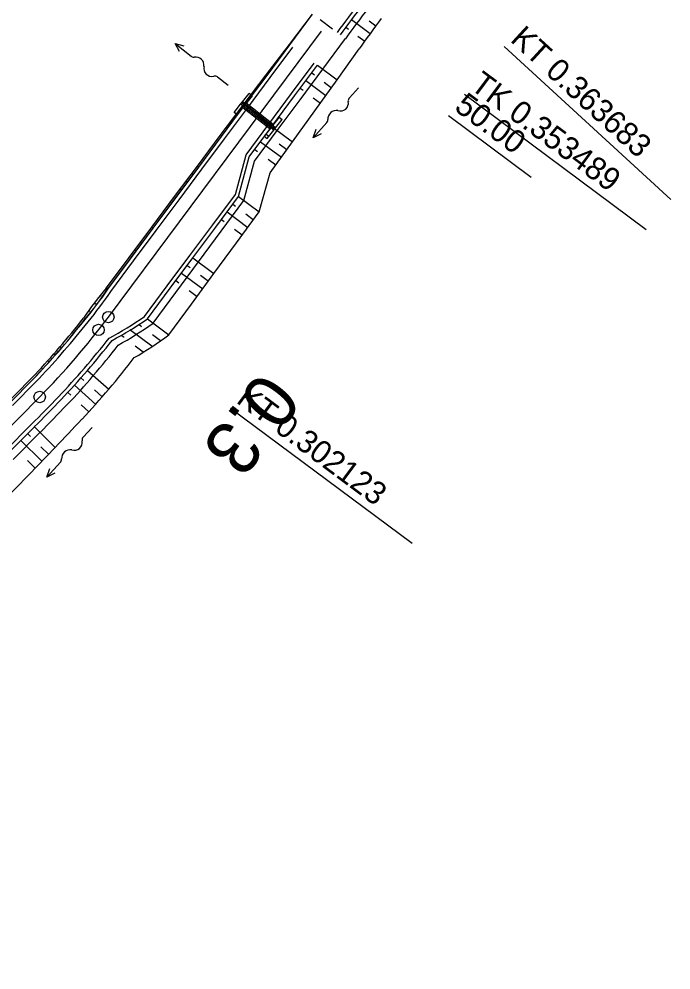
# Model space of a CAD drawing. Extents: x -481656 to -478728, y -1113199 to -1110710.
# Drawn here: x -479712.7 to -479627.2, y -1111634.8 to -1111510 of the extents above; entities that cross this region are included whole.
import ezdxf

# ---------------------------------------------------------------- set-up
doc = ezdxf.new("R2010")
doc.units = 0
for name, color, linetype in [('C5_HATCH_SLOPE_L', 7, 'Continuous'), ('C5_HATCH_SLOPE_R', 7, 'Continuous'), ('C5_HECTOMETRY', 7, 'Continuous'), ('C5_HLBODY', 7, 'Continuous'), ('C5_HRANA_TELESO', 7, 'Continuous'), ('C5_KORUNA', 7, 'Continuous'), ('C5_OSA', 7, 'Continuous'), ('C5_PRIKOP', 7, 'Continuous'), ('C5_STANICENI', 7, 'Continuous'), ('C5_ZPEVKRAJ', 7, 'Continuous'), ('DRENÁŽ', 7, 'Continuous'), ('PLYN', 7, 'Continuous'), ('ŽLAB', 7, 'Continuous')]:
    doc.layers.add(name, color=color, linetype=linetype)

# ---------------------------------------------------------------- blocks, each defined once
blk = doc.blocks.new('A$C716')
at = {"layer": 'ŽLAB'}
for p, q in [((-5.015, 2.333), (-4.471, 3.623)), ((-4.01, 3.428), (-4.554, 2.138)), ((-4.01, 3.428), (-4.471, 3.623)), ((-5.715, 0.674), (-5.17, 1.964)), ((-4.71, 1.77), (-5.254, 0.48)), ((-0.078, -0.184), (-5.171, 1.964)), ((-5.17, 1.964), (-5.015, 2.333)), ((-4.71, 1.77), (-5.17, 1.964)), ((0, 0), (-5.093, 2.148)), ((-5.015, 2.333), (-0.383, 0.379)), ((-4.554, 2.138), (-5.015, 2.333)), ((-4.768, 1.632), (-0.597, -0.128)), ((-0.325, 0.517), (-4.496, 2.277)), ((0.161, 1.669), (-0.383, 0.379)), ((0.078, 0.184), (0.622, 1.474)), ((0.161, 1.669), (0.622, 1.474)), ((-5.254, 0.48), (-5.715, 0.674)), ((-0.538, 0.01), (-1.083, -1.28)), ((-0.078, -0.184), (-0.999, 0.204)), ((0.078, 0.184), (-0.844, 0.573)), ((-0.538, 0.01), (-0.383, 0.379)), ((-0.078, -0.184), (0.078, 0.184)), ((-0.622, -1.474), (-0.078, -0.184)), ((-1.083, -1.28), (-0.622, -1.474))]:
    blk.add_line(p, q, dxfattribs=at)
blk = doc.blocks.new('A$C70B')
at = {"layer": 'DRENÁŽ'}
for p, q in [((0.87, 0), (-0.87, 0)), ((6.86, 0.43), (7.97, 0)), ((7.97, 0), (5.28, 0)), ((7.97, 0), (6.86, -0.48))]:
    blk.add_line(p, q, dxfattribs=at)
for centre, radius, start, end in [((0.87, 0.58), 0.582, 269.6924, 322.7901), ((2.17, -0.42), 1.05, 24.4039, 142.0836), ((4.08, 0.59), 1.11, 210.8873, 317.3707), ((5.32, -0.64), 0.636, 85.9766, 131.7248)]:
    blk.add_arc(centre, radius, start, end, dxfattribs=at)

msp = doc.modelspace()

# ---------------------------------------------------------------- linework, layer by layer
at = {"layer": 'C5_HATCH_SLOPE_L'}
for p, q in [((-479677.2, -1111513.36), (-479677.31, -1111513.28)), ((-479678.7, -1111515.37), (-479678.83, -1111515.27)), ((-479678.01, -1111514.32), (-479678.07, -1111514.28)), ((-479677.95, -1111514.37), (-479677.96, -1111514.36)), ((-479679.52, -1111516.31), (-479679.59, -1111516.26)), ((-479679.45, -1111516.37), (-479679.45, -1111516.37)), ((-479683.18, -1111521.38), (-479683.37, -1111521.24)), ((-479684.02, -1111522.31), (-479684.11, -1111522.24)), ((-479683.93, -1111522.39), (-479683.93, -1111522.38)), ((-479684.67, -1111523.39), (-479684.86, -1111523.25)), ((-479685.52, -1111524.32), (-479685.61, -1111524.25)), ((-479685.42, -1111524.39), (-479685.42, -1111524.39)), ((-479690, -1111530.33), (-479690.09, -1111530.26)), ((-479689.15, -1111529.4), (-479689.34, -1111529.26)), ((-479690.65, -1111531.41), (-479690.84, -1111531.26)), ((-479689.9, -1111530.4), (-479689.9, -1111530.4)), ((-479691.49, -1111532.33), (-479691.59, -1111532.27)), ((-479691.39, -1111532.41), (-479691.4, -1111532.41)), ((-479695.13, -1111537.42), (-479695.32, -1111537.28)), ((-479695.98, -1111538.35), (-479696.07, -1111538.28)), ((-479695.88, -1111538.42), (-479695.88, -1111538.42)), ((-479696.62, -1111539.43), (-479696.82, -1111539.28)), ((-479697.47, -1111540.35), (-479697.56, -1111540.28)), ((-479697.37, -1111540.43), (-479697.37, -1111540.42)), ((-479701.95, -1111546.36), (-479702.05, -1111546.29)), ((-479701.85, -1111546.44), (-479701.85, -1111546.44)), ((-479701.1, -1111545.44), (-479701.3, -1111545.29)), ((-479702.6, -1111547.44), (-479702.8, -1111547.29)), ((-479703.44, -1111548.35), (-479703.54, -1111548.28)), ((-479703.34, -1111548.43), (-479703.34, -1111548.43)), ((-479708.08, -1111554.01), (-479708.17, -1111553.93)), ((-479707.18, -1111553.18), (-479707.37, -1111553.01)), ((-479708.8, -1111555.01), (-479708.98, -1111554.84)), ((-479707.98, -1111554.1), (-479707.98, -1111554.09)), ((-479709.72, -1111555.82), (-479709.81, -1111555.73)), ((-479709.62, -1111555.91), (-479709.63, -1111555.9))]:
    msp.add_line(p, q, dxfattribs=at)
at = {"layer": 'C5_HATCH_SLOPE_R'}
for p, q in [((-479669.11, -1111510.04), (-479666.66, -1111511.87)), ((-479666.81, -1111510.21), (-479665.93, -1111510.87)), ((-479669.86, -1111511.04), (-479669.52, -1111511.29)), ((-479668.28, -1111512.22), (-479667.39, -1111512.89)), ((-479673.6, -1111516.05), (-479671.02, -1111517.97)), ((-479674.34, -1111517.05), (-479673.99, -1111517.31)), ((-479675.09, -1111518.06), (-479672.48, -1111520.01)), ((-479672.7, -1111518.28), (-479671.75, -1111518.99)), ((-479675.84, -1111519.06), (-479675.48, -1111519.32)), ((-479674.17, -1111520.3), (-479673.2, -1111521.02)), ((-479680.32, -1111525.07), (-479679.96, -1111525.34)), ((-479679.57, -1111524.07), (-479676.85, -1111526.09)), ((-479681.06, -1111526.08), (-479678.32, -1111528.12)), ((-479678.59, -1111526.36), (-479677.59, -1111527.11)), ((-479681.81, -1111527.08), (-479681.45, -1111527.35)), ((-479680.07, -1111528.38), (-479679.05, -1111529.13)), ((-479683.94, -1111533.28), (-479681.23, -1111535.3)), ((-479684.69, -1111534.29), (-479684.33, -1111534.55)), ((-479686.18, -1111536.29), (-479685.83, -1111536.56)), ((-479685.43, -1111535.29), (-479682.71, -1111537.32)), ((-479682.98, -1111535.56), (-479681.97, -1111536.31)), ((-479684.46, -1111537.57), (-479683.45, -1111538.32)), ((-479689.92, -1111541.3), (-479687.16, -1111543.36)), ((-479690.66, -1111542.31), (-479690.3, -1111542.58)), ((-479691.41, -1111543.31), (-479688.63, -1111545.38)), ((-479688.91, -1111543.61), (-479687.89, -1111544.37)), ((-479692.16, -1111544.31), (-479691.79, -1111544.59)), ((-479690.4, -1111545.62), (-479689.37, -1111546.38)), ((-479697.04, -1111550.03), (-479696.66, -1111550.31)), ((-479695.89, -1111549.32), (-479693.07, -1111551.42)), ((-479699.35, -1111551.45), (-479698.96, -1111551.75)), ((-479698.19, -1111550.73), (-479695.3, -1111552.88)), ((-479695.23, -1111551.37), (-479694.19, -1111552.15)), ((-479697.51, -1111552.85), (-479696.46, -1111553.65)), ((-479703.77, -1111556.11), (-479700.95, -1111558.55)), ((-479704.61, -1111557.08), (-479704.23, -1111557.42)), ((-479705.46, -1111558.03), (-479702.68, -1111560.55)), ((-479702.83, -1111558.65), (-479701.81, -1111559.55)), ((-479706.33, -1111558.97), (-479705.95, -1111559.32)), ((-479704.57, -1111560.6), (-479703.57, -1111561.53)), ((-479710.73, -1111563.5), (-479708, -1111566.2)), ((-479711.61, -1111564.39), (-479711.24, -1111564.76)), ((-479712.49, -1111565.28), (-479709.73, -1111568)), ((-479709.86, -1111566.11), (-479708.87, -1111567.1)), ((-479711.61, -1111567.91), (-479710.6, -1111568.9))]:
    msp.add_line(p, q, dxfattribs=at)
at = {"layer": 'C5_HECTOMETRY'}
msp.add_circle((-479702.3, -1111550.78), 0.75, dxfattribs=at)
at = {"layer": 'C5_HLBODY'}
for p, q in [((-479649.09, -1111513.57), (-479627.21, -1111533.65)), ((-479654.29, -1111519.85), (-479630.47, -1111537.59)), ((-479684.98, -1111561.04), (-479661.16, -1111578.78))]:
    msp.add_line(p, q, dxfattribs=at)
for centre in [(-479701.02, -1111549.09), (-479710.03, -1111559.58)]:
    msp.add_circle(centre, 0.75, dxfattribs=at)
at = {"layer": 'C5_HRANA_TELESO'}
for p, q in [((-479677.27, -1111513.31), (-479674.23, -1111509.34)), ((-479680.31, -1111517.28), (-479677.27, -1111513.31)), ((-479671.02, -1111517.97), (-479668.11, -1111513.9)), ((-479683.34, -1111521.26), (-479680.31, -1111517.28)), ((-479673.93, -1111522.04), (-479671.02, -1111517.97)), ((-479686.33, -1111525.27), (-479683.34, -1111521.26)), ((-479676.85, -1111526.09), (-479673.93, -1111522.04)), ((-479689.33, -1111529.27), (-479686.33, -1111525.27)), ((-479679.79, -1111530.15), (-479676.85, -1111526.09)), ((-479692.32, -1111533.28), (-479689.33, -1111529.27)), ((-479681.23, -1111535.3), (-479679.79, -1111530.15)), ((-479695.32, -1111537.28), (-479692.32, -1111533.28)), ((-479684.19, -1111539.33), (-479681.23, -1111535.3)), ((-479698.31, -1111541.28), (-479695.32, -1111537.28)), ((-479687.16, -1111543.36), (-479684.19, -1111539.33)), ((-479701.31, -1111545.29), (-479698.31, -1111541.28)), ((-479690.11, -1111547.39), (-479687.16, -1111543.36)), ((-479693.07, -1111551.42), (-479690.11, -1111547.39)), ((-479711.47, -1111569.8), (-479708, -1111566.2)), ((-479714.93, -1111573.4), (-479711.47, -1111569.8))]:
    msp.add_line(p, q, dxfattribs=at)
for centre, radius, start, end in [((-479436.28, -1111678.25), 284.18, 143.6746, 144.6667), ((-479663.95, -1111576.59), 48.74, 140.0386, 145.8556), ((-479781.28, -1111489.44), 97.49, 319.3, 322.1647), ((-479724.41, -1111508.73), 52.96, 300.3782, 306.281), ((-479781.31, -1111489.46), 97.5, 316.4548, 319.3196), ((-479781.84, -1111490.12), 105.95, 319.7732, 322.6381), ((-479921.26, -1111353.66), 292.5, 315.0894, 316.0604), ((-479781.9, -1111490.11), 106, 316.9239, 319.7889), ((-479936.09, -1111344.5), 318.07, 315.8147, 316.7342)]:
    msp.add_arc(centre, radius, start, end, dxfattribs=at)
at = {"layer": 'C5_KORUNA'}
for p, q in [((-479680.19, -1111517.37), (-479677.2, -1111513.36)), ((-479676.58, -1111520.06), (-479673.6, -1111516.05)), ((-479683.18, -1111521.38), (-479680.19, -1111517.37)), ((-479679.57, -1111524.07), (-479676.58, -1111520.06)), ((-479686.17, -1111525.39), (-479683.18, -1111521.38)), ((-479682.56, -1111528.08), (-479679.57, -1111524.07)), ((-479689.15, -1111529.4), (-479686.17, -1111525.39)), ((-479683.94, -1111533.28), (-479682.56, -1111528.08)), ((-479692.14, -1111533.41), (-479689.15, -1111529.4)), ((-479695.13, -1111537.42), (-479692.14, -1111533.41)), ((-479686.93, -1111537.29), (-479683.94, -1111533.28)), ((-479698.12, -1111541.43), (-479695.13, -1111537.42)), ((-479689.92, -1111541.3), (-479686.93, -1111537.29)), ((-479701.1, -1111545.44), (-479698.12, -1111541.43)), ((-479692.9, -1111545.31), (-479689.92, -1111541.3)), ((-479695.89, -1111549.32), (-479692.9, -1111545.31)), ((-479714.24, -1111567.06), (-479710.73, -1111563.5))]:
    msp.add_line(p, q, dxfattribs=at)
for centre, radius, start, end in [((-479434.37, -1111685.79), 293.25, 142.6969, 143.6672), ((-479741.6, -1111518.08), 48.88, 320.1521, 325.9599), ((-479781.21, -1111489.34), 97.75, 319.2297, 322.0945), ((-479724.86, -1111507.2), 51.12, 298.4217, 304.5189), ((-479781.21, -1111489.34), 102.25, 319.2297, 322.0945), ((-479781.21, -1111489.34), 97.75, 316.3649, 319.2297), ((-479781.21, -1111489.34), 102.25, 316.3649, 319.2297), ((-479921.52, -1111353.2), 293.25, 315.0613, 316.0307), ((-479927.94, -1111346.9), 306.75, 315.0804, 316.0216)]:
    msp.add_arc(centre, radius, start, end, dxfattribs=at)
at = {"layer": 'C5_OSA'}
for p, q in [((-479701.02, -1111549.09), (-479673.05, -1111511.56)), ((-479784.24, -1111634.78), (-479710.03, -1111559.58))]:
    msp.add_line(p, q, dxfattribs=at)
msp.add_arc((-479781.21, -1111489.34), 100, 315.3788, 323.3108, dxfattribs=at)
at = {"layer": 'C5_PRIKOP'}
for p, q in [((-479677.21, -1111513.36), (-479674.23, -1111509.35)), ((-479672.9, -1111516.57), (-479669.92, -1111512.55)), ((-479680.2, -1111517.37), (-479677.21, -1111513.36)), ((-479683.19, -1111521.38), (-479680.2, -1111517.37)), ((-479675.87, -1111520.59), (-479672.9, -1111516.57)), ((-479686.17, -1111525.39), (-479683.19, -1111521.38)), ((-479678.85, -1111524.61), (-479675.87, -1111520.59)), ((-479681.83, -1111528.63), (-479678.85, -1111524.61)), ((-479689.16, -1111529.4), (-479686.17, -1111525.39)), ((-479683.24, -1111533.81), (-479681.83, -1111528.63)), ((-479692.15, -1111533.41), (-479689.16, -1111529.4)), ((-479695.14, -1111537.41), (-479692.15, -1111533.41)), ((-479686.21, -1111537.83), (-479683.24, -1111533.81)), ((-479698.12, -1111541.42), (-479695.14, -1111537.41)), ((-479689.19, -1111541.85), (-479686.21, -1111537.83)), ((-479701.11, -1111545.43), (-479698.12, -1111541.42)), ((-479692.16, -1111545.86), (-479689.19, -1111541.85)), ((-479695.14, -1111549.88), (-479692.16, -1111545.86)), ((-479713.49, -1111567.8), (-479709.99, -1111564.24))]:
    msp.add_line(p, q, dxfattribs=at)
for centre, radius, start, end in [((-479435.19, -1111684.09), 290.73, 142.8656, 143.8418), ((-479741.61, -1111518.08), 48.87, 320.1519, 325.9601), ((-479781.21, -1111489.34), 97.74, 319.2297, 322.0945), ((-479724.9, -1111507.7), 51.63, 299.1686, 305.2022), ((-479781.21, -1111489.34), 97.74, 316.3649, 319.2297), ((-479781.39, -1111489.57), 103.26, 319.3938, 322.2586), ((-479921.5, -1111353.22), 293.22, 315.0613, 316.0307), ((-479781.4, -1111489.56), 103.28, 316.529, 319.3938), ((-479930.04, -1111346.1), 309.85, 315.2518, 316.1869)]:
    msp.add_arc(centre, radius, start, end, dxfattribs=at)
at = {"layer": 'C5_STANICENI'}
for p, q in [((-479671.61, -1111511.3), (-479673.21, -1111510.1)), ((-479656.38, -1111522.65), (-479645.55, -1111530.71))]:
    msp.add_line(p, q, dxfattribs=at)
at = {"layer": 'C5_ZPEVKRAJ'}
for p, q in [((-479679.79, -1111517.67), (-479676.8, -1111513.66)), ((-479676.98, -1111519.76), (-479674, -1111515.75)), ((-479682.78, -1111521.68), (-479679.79, -1111517.67)), ((-479679.97, -1111523.77), (-479676.98, -1111519.76)), ((-479685.77, -1111525.69), (-479682.78, -1111521.68)), ((-479682.96, -1111527.78), (-479679.97, -1111523.77)), ((-479688.75, -1111529.7), (-479685.77, -1111525.69)), ((-479684.34, -1111532.99), (-479682.96, -1111527.78)), ((-479691.74, -1111533.71), (-479688.75, -1111529.7)), ((-479694.73, -1111537.72), (-479691.74, -1111533.71)), ((-479687.33, -1111537), (-479684.34, -1111532.99)), ((-479697.72, -1111541.73), (-479694.73, -1111537.72)), ((-479690.32, -1111541.01), (-479687.33, -1111537)), ((-479693.3, -1111545.01), (-479690.32, -1111541.01)), ((-479700.7, -1111545.74), (-479697.72, -1111541.73)), ((-479696.29, -1111549.02), (-479693.3, -1111545.01)), ((-479714.6, -1111566.71), (-479711.09, -1111563.15))]:
    msp.add_line(p, q, dxfattribs=at)
for centre, radius, start, end in [((-479433.57, -1111686.38), 294.75, 142.6982, 143.665), ((-479741.4, -1111518.23), 49.12, 320.1599, 325.9506), ((-479781.21, -1111489.34), 98.25, 319.2297, 322.0945), ((-479725.1, -1111507.09), 50.88, 298.3718, 304.4877), ((-479781.21, -1111489.34), 101.75, 319.2297, 322.0945), ((-479781.21, -1111489.34), 98.25, 316.3649, 319.2297), ((-479781.21, -1111489.34), 101.75, 316.3649, 319.2297), ((-479922.23, -1111352.5), 294.75, 315.0635, 316.0296), ((-479927.23, -1111347.6), 305.25, 315.0784, 316.0226)]:
    msp.add_arc(centre, radius, start, end, dxfattribs=at)

# ---------------------------------------------------------------- block references
at = {"layer": 'PLYN'}
for p, rotation in [((-479686, -1111518.12), 141.9290545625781), ((-479668.8, -1111519.67), -132.33894913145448), ((-479703.73, -1111564.21), -132.33894913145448)]:
    msp.add_blockref('A$C70B', p, dxfattribs=dict(at, rotation=rotation))
at = {"layer": 'ŽLAB', "rotation": -15.3131081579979}
msp.add_blockref('A$C716', (-479679.2, -1111524.41), dxfattribs=at)

# ---------------------------------------------------------------- texts
at = {"layer": 'C5_HECTOMETRY'}
msp.add_text('0.3', height=6.999, rotation=232.0489, dxfattribs=at).set_placement((-479680.96, -1111555.94))
at = {"layer": 'C5_HLBODY'}
for s, height, rotation, p in [('KT 0.363683', 2.999, 317.4702, (-479648.42, -1111512.83)), ('TK 0.353489', 3, 323.3109, (-479653.69, -1111519.05)), ('KT 0.302123', 3, 323.3109, (-479684.38, -1111560.24))]:
    msp.add_text(s, height=height, rotation=rotation, dxfattribs=at).set_placement(p)
at = {"layer": 'C5_STANICENI'}
msp.add_text('50.00', height=3, rotation=323.3109, dxfattribs=at).set_placement((-479655.78, -1111521.84))

doc.saveas('drawing.dxf')
